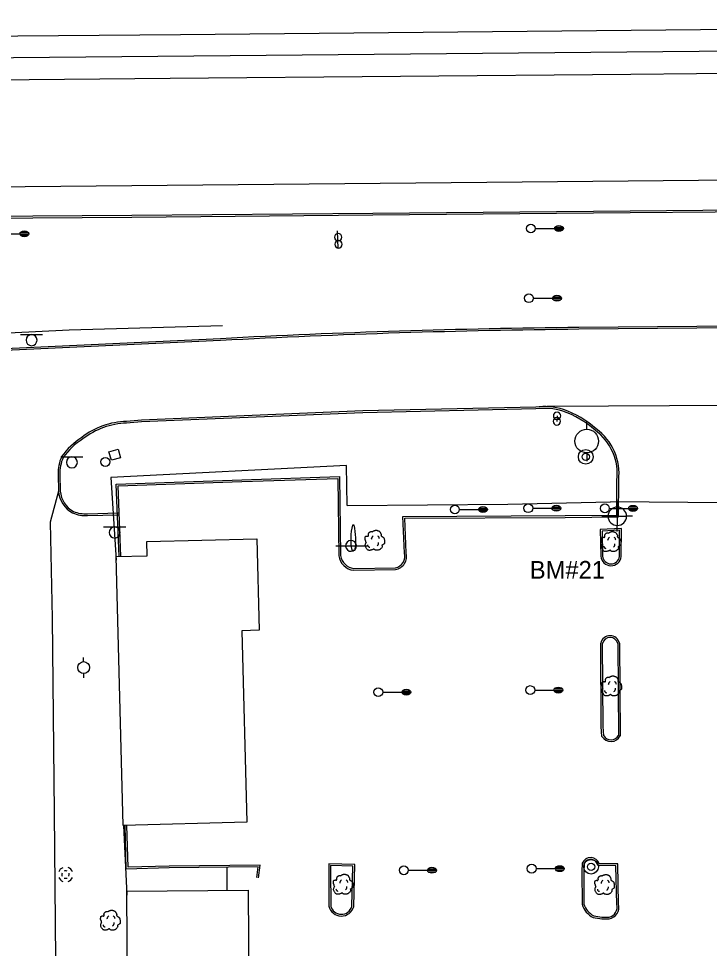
# Model space of a CAD drawing. Extents: x 2145380 to 2156929, y 139568 to 149130.
# Drawn here: x 2148024.6 to 2148258.3, y 142765.5 to 143079.9 of the extents above; entities that cross this region are included whole.
import ezdxf

# ---------------------------------------------------------------- set-up
doc = ezdxf.new("R2010")
doc.units = 0
for name, color, linetype in [('Default', 7, 'Continuous'), ('SURV_Benchmark', 7, 'Continuous'), ('SURV_Text', 7, 'Continuous'), ('TOPO_Asphalt', 7, 'Continuous'), ('TOPO_Building', 7, 'Continuous'), ('TOPO_Concrete', 7, 'Continuous'), ('TOPO_Curb Back', 7, 'Continuous'), ('TOPO_DRAIN_Manhole', 7, 'Continuous'), ('TOPO_Fence', 7, 'Continuous'), ('TOPO_Guardrail', 7, 'Continuous'), ('TOPO_Light Pole', 7, 'Continuous'), ('TOPO_Misc', 7, 'Continuous'), ('TOPO_Power Pole', 7, 'Continuous'), ('TOPO_San Manhole', 7, 'Continuous'), ('TOPO_Sign', 7, 'Continuous'), ('TOPO_Tree', 7, 'Continuous'), ('TOPO_Wall Freestanding', 7, 'Continuous'), ('TOPO_Water Meter', 7, 'Continuous')]:
    doc.layers.add(name, color=color, linetype=linetype)

# ---------------------------------------------------------------- blocks, each defined once
blk = doc.blocks.new('LP')
at = {"layer": 'TOPO_Light Pole'}
blk.add_line((3.81, 0), (20.32, 0), dxfattribs=at)
for points in [[(20.32, 0), (27.94, 0)], [(20.32, 0), (23.5, 0)], [(20.83, 1.27), (27.43, 1.27)], [(20.83, 1.27), (23.5, 1.27)], [(23.71, 1.27), (27.43, 1.27)], [(23.71, 0), (27.94, 0)], [(20.83, -1.27), (27.43, -1.27)], [(20.83, -1.27), (23.5, -1.27)], [(23.71, -1.27), (27.43, -1.27)]]:
    blk.add_lwpolyline(points, dxfattribs=at)
blk.add_circle((0, 0), 3.81, dxfattribs=at)
blk.add_ellipse((24.13, 0), major_axis=(3.81, 0), ratio=0.666667, dxfattribs=at)
blk = doc.blocks.new('POST')
at = {"layer": 'TOPO_Misc'}
for start, end in [(89.99996, 180.00004), (179.99996, 270.00004), (359.99996, 90.00004), (269.99996, 0.00004)]:
    blk.add_arc((-0.01, 0.03), 3.16, start, end, dxfattribs=at)
blk = doc.blocks.new('MHEXST')
at = {"layer": 'TOPO_DRAIN_Manhole'}
for centre, radius, start, end in [((-0.1, 0.3), 12.7, 112.9748, 158.2636), ((-0.1, 0.1), 6.35, 157.9722, 204.161), ((-0.1, 0.1), 6.35, 66.1941, 113.691), ((-0.1, 0.3), 12.7, 22.0744, 68.6991), ((-0.1, 0.1), 6.35, 336.8023, 21.4046), ((-0.1, 0.3), 12.7, 202.6921, 248.1938), ((-0.1, 0.1), 6.35, 248.5791, 293.1995), ((-0.1, 0.3), 12.7, 291.7963, 337.3032)]:
    blk.add_arc(centre, radius, start, end, dxfattribs=at)
blk = doc.blocks.new('POWPOL')
at = {"layer": 'TOPO_Power Pole'}
for p, q in [((0, 10.16), (0, 17.34)), ((0, -10.16), (0, -17.34))]:
    blk.add_line(p, q, dxfattribs=at)
blk.add_circle((0, 0), 10.16, dxfattribs=at)
blk = doc.blocks.new('TREE')
at = {"layer": 'TOPO_Tree'}
for points in [[(-14.1, -0.4), (-14.2, 0.5), (-14.4, 1.4), (-14.6, 2.3), (-14.8, 3.2), (-15.5, 4), (-15.7, 4.9), (-15.8, 5.6), (-15.7, 6.3), (-15.7, 7), (-15.6, 7.9), (-15.7, 8.8), (-15.1, 9.7), (-14.6, 10.4), (-13.8, 10.5), (-13, 10.7), (-12.2, 11), (-11.1, 10), (-10.4, 10.7), (-9.4, 11.7), (-10.3, 13.3), (-9.8, 14.4), (-9.6, 15.1), (-9.3, 15.9), (-8.8, 16.5), (-8.2, 17.3), (-7.5, 17.7), (-6.7, 18.1), (-6.1, 18.4), (-5.6, 18.6), (-5.1, 18.7), (-4.5, 18.7), (-4, 18.5), (-3.5, 18.1)], [(-3.5, 17.6), (-3.1, 18.3), (-2.6, 18.8), (-1.9, 19.2), (-1, 19.7), (-0.2, 20), (0.7, 20.2), (1.6, 20.5), (2.5, 20.8), (3.4, 20.8), (4.1, 20.7), (4.8, 20.5), (5.5, 20.2), (6.4, 19.9), (7.3, 19.7), (8.2, 19.2), (9.4, 18.4), (10, 17.2), (10.8, 16), (11.2, 15.3), (11.6, 14.6), (11.9, 13.9), (12.2, 13.1), (11.4, 12), (11.9, 11.2), (12, 11), (12.2, 10.9), (12.4, 10.7), (12.9, 10.4), (13.5, 10), (14, 9.7), (14.7, 9.2), (15.4, 8.7), (16.1, 8.1), (16.7, 7.5), (16.9, 6.7), (17.1, 6), (17.6, 4.4), (17.7, 2.8), (17.7, 1.2), (17.7, -0.2), (17.8, -2.2), (16.6, -3), (15.5, -3.8), (14.3, -4.6), (13.2, -5.3)], [(13.2, -5.3), (13.3, -5.8), (13.4, -6.3), (13.4, -6.7), (13.8, -8.5), (12.2, -10), (10.8, -11.5), (10, -12.3), (9.1, -12.8), (8.2, -13.1), (6, -13.8), (3.3, -13.6), (1.3, -13.1), (0.5, -12.9), (-0.1, -11.4), (-0.8, -11.5), (-2, -11.6), (-3.3, -12.8), (-4.5, -13.1), (-6.1, -13.5), (-7.8, -14), (-9.3, -13.6), (-11.4, -13.1), (-12.8, -11.4), (-14.1, -9.4), (-15.3, -7.3), (-15.6, -5.1), (-15.1, -3), (-14.9, -1.9), (-13.9, -0.8), (-13.5, 0.1)], [(-4.2, 5.1), (-4.5, 6.1), (-4.3, 7.2), (-3.8, 8.2), (-3.3, 9.3), (-2.7, 10.3), (-1.6, 11)], [(5.9, 11.2), (6.5, 10.7), (7, 10.2), (7.4, 9.5), (7.9, 8.6), (8.3, 7.6), (8.5, 6.6)], [(-11.4, -4.5), (-11.5, -5.4), (-11, -6.3), (-10.1, -7.2), (-9.3, -8), (-8.5, -8.3), (-7.7, -8.1)], [(4.8, -6.3), (5.7, -5.7), (6.3, -4.9), (6.8, -3.9), (7.4, -2.8), (7.6, -1.7), (7.5, -0.6)]]:
    blk.add_open_spline(points, degree=3, dxfattribs=at)
blk = doc.blocks.new('WTRMTR')
at = {"layer": 'Default'}
blk.add_circle((0, 0), 3.89, dxfattribs=at)
blk = doc.blocks.new('EXMHSS')
at = {"layer": 'Default'}
for radius in [6.3, 3.13]:
    blk.add_circle((0, 0), radius, dxfattribs=at)
blk = doc.blocks.new('BM')
at = {"layer": 'SURV_Benchmark'}
for p, q in [((0, 2.49), (0, 4.15)), ((-2.49, 0), (-4.16, 0)), ((4.16, 0), (2.49, 0)), ((0, -4.16), (0, -2.49))]:
    blk.add_line(p, q, dxfattribs=at)
for points in [[(-2.5, 0), (-2.49, 0), (0, 0), (0, -2.49), (0, -2.49)], [(-2.5, 0), (-2.49, 0), (0, 0), (0, -2.49), (0, -2.49)], [(0, 2.49), (0, 2.49), (0, 0), (2.49, 0), (2.49, 0), (2.49, 0)], [(0, 2.49), (0, 2.49), (0, 0), (2.49, 0), (2.49, 0), (2.49, 0), (2.49, 0)]]:
    blk.add_lwpolyline(points, dxfattribs=at)
for start, end in [(90.0638, 180.0068), (0.0638, 90.0068), (0.0638, 90.0068), (180.0638, 270.0068), (180.0638, 270.0068), (269.9472, 359.9927)]:
    blk.add_arc((0, 0), 2.5, start, end, dxfattribs=at)

msp = doc.modelspace()

# ---------------------------------------------------------------- linework, layer by layer
at = {"layer": 'TOPO_Asphalt'}
for p, q in [((2148286.72, 142949.26), (2148203.43, 142948.67)), ((2148095.16, 142785.11), (2148095.15, 142792.95))]:
    msp.add_line(p, q, dxfattribs=at)
for points in [[(2147470.58, 143069.33), (2147522.83, 143069.63), (2147583.04, 143070.11), (2147738.8, 143071.51), (2147927.95, 143073.19), (2148079.29, 143074.53), (2148267.02, 143076.34), (2148475.01, 143078.41), (2148538.91, 143078.92), (2148589.31, 143079.37), (2148643.94, 143079.86)], [(2148645.25, 143065.02), (2148587.42, 143064.51), (2148537.54, 143063.98), (2148499.94, 143063.7), (2148475.32, 143063.38), (2148365.01, 143062.26), (2148231.65, 143061), (2148075.9, 143059.61), (2147932.72, 143058.25), (2147796.35, 143057.04), (2147634.21, 143055.45), (2147582.22, 143054.84), (2147523.45, 143054.49), (2147473.54, 143053.84), (2147431.18, 143053.29), (2147414.12, 143053.17)], [(2147589.87, 143018.81), (2147717.93, 143020.11), (2147869.31, 143021.64), (2148038.91, 143023.21), (2148194.98, 143024.71), (2148374.01, 143026.39), (2148492.71, 143027.39), (2148574.25, 143028.13), (2148490.61, 143015.81), (2148430.33, 143006.91), (2148411.96, 143003.93)], [(2148038.06, 142920.06), (2148035.23, 142909.56), (2148035.92, 142877.2), (2148036.59, 142811.48), (2148037.06, 142761.73), (2148035.76, 142724.53), (2148048.83, 142712.9)]]:
    msp.add_lwpolyline(points, dxfattribs=at)
at = {"layer": 'TOPO_Building'}
for points in [[(2148060, 142807.05), (2148057.58, 142897.95), (2148068.06, 142898.23), (2148067.93, 142903.04), (2148105.16, 142904.03), (2148105.98, 142873.09), (2148100.05, 142872.93), (2148101.78, 142808.16)], [(2148102.22, 142785.16), (2148102.61, 142734.02), (2148061.58, 142733.7), (2148061.19, 142784.84)]]:
    msp.add_lwpolyline(points, close=True, dxfattribs=at)
at = {"layer": 'TOPO_Concrete'}
msp.add_lwpolyline([(2148058.25, 142934.32), (2148059.01, 142931.38), (2148055.95, 142930.55), (2148055.09, 142933.36), (2148058.25, 142934.32)], dxfattribs=at)
at = {"layer": 'TOPO_Curb Back'}
for p, q in [((2148228.5, 142907.48), (2148221.33, 142907.18)), ((2148221.33, 142907.18), (2148221.52, 142898.08)), ((2148227.9, 142906.86), (2148221.94, 142906.61)), ((2148221.94, 142906.61), (2148222.12, 142898.11)), ((2148227.82, 142898), (2148227.9, 142906.86)), ((2148228.42, 142897.96), (2148228.5, 142907.48)), ((2148221.7, 142840.5), (2148221.51, 142868.68)), ((2148222.3, 142840.52), (2148222.11, 142868.62)), ((2148227.26, 142868.62), (2148227.49, 142837.52)), ((2148227.86, 142868.69), (2148228.09, 142837.37)), ((2148221.93, 142837.18), (2148221.7, 142840.5)), ((2148222.52, 142837.37), (2148222.3, 142840.52)), ((2148138.29, 142793.84), (2148129.51, 142794.13)), ((2148129.51, 142794.13), (2148129.52, 142792.06)), ((2148137.68, 142793.26), (2148130.11, 142793.51)), ((2148130.11, 142793.51), (2148130.12, 142792.07)), ((2148137.34, 142779.71), (2148137.68, 142793.26)), ((2148137.93, 142779.62), (2148138.29, 142793.84)), ((2148215.28, 142794.34), (2148215.15, 142791.46)), ((2148215.88, 142794.2), (2148215.75, 142791.45)), ((2148226.66, 142793.46), (2148220.53, 142793.49)), ((2148227.25, 142794.06), (2148221.01, 142794.09)), ((2148226.96, 142780.37), (2148226.66, 142793.46)), ((2148227.56, 142780.45), (2148227.25, 142794.06)), ((2148129.52, 142792.06), (2148129.55, 142779.77)), ((2148130.12, 142792.07), (2148130.15, 142779.84)), ((2148215.15, 142791.46), (2148215.19, 142780.42)), ((2148215.75, 142791.45), (2148215.79, 142780.51)), ((2148221.89, 142775.51), (2148224.41, 142775.5)), ((2148221.94, 142776.11), (2148224.35, 142776.1))]:
    msp.add_line(p, q, dxfattribs=at)
for points in [[(2147481.17, 143008.11), (2147525.22, 143008.77), (2147576.01, 143008.92), (2147591.08, 143009.11), (2147697.75, 143010.22), (2147838.49, 143011.59), (2147962.13, 143012.69), (2148062.91, 143013.36), (2148144.44, 143014.07), (2148231.43, 143014.88), (2148317.67, 143015.61), (2148394.72, 143016.3), (2148452.05, 143016.97)], [(2147481.18, 143007.51), (2147525.22, 143008.17), (2147576.02, 143008.32), (2147591.09, 143008.51), (2147697.75, 143009.62), (2147838.5, 143010.99), (2147962.13, 143012.09), (2148062.91, 143012.76), (2148144.45, 143013.47), (2148231.43, 143014.28), (2148317.68, 143015.01), (2148394.72, 143015.7), (2148452.1, 143016.37)], [(2148286.43, 142976.24), (2148254.06, 142975.75), (2148214.13, 142975.42)], [(2148286.43, 142975.64), (2148254.06, 142975.15), (2148214.13, 142974.82)], [(2148092.84, 142971.64), (2148022.41, 142968.38), (2147893.34, 142962.43), (2147794.24, 142957.82), (2147684.33, 142952.92), (2147578.17, 142948.11)], [(2148092.87, 142971.04), (2148022.44, 142967.78), (2147893.36, 142961.84), (2147794.27, 142957.22), (2147684.36, 142952.32), (2147578.2, 142947.51)], [(2148199.53, 142948.51), (2148140.98, 142947.2), (2148066.1, 142944.1), (2148061.08, 142943.67)], [(2148199.58, 142947.91), (2148141, 142946.6), (2148066.13, 142943.5), (2148061.11, 142943.07)], [(2148037.95, 142925.7), (2148038.06, 142920.06)], [(2148038.55, 142925.72), (2148038.66, 142920.09)], [(2148058.56, 142897.97), (2148057.62, 142922.43), (2148100.06, 142923.97), (2148133.15, 142925.02), (2148133.45, 142898.29)], [(2148059.16, 142897.99), (2148058.24, 142921.86), (2148100.08, 142923.37), (2148132.56, 142924.4), (2148132.86, 142898.23)], [(2148155.08, 142899.11), (2148154.59, 142911.52), (2148209.52, 142911.84), (2148226.96, 142911.97), (2148226.98, 142923.81)], [(2148155.67, 142899.2), (2148155.22, 142910.92), (2148209.53, 142911.24), (2148227.56, 142911.37), (2148227.58, 142923.77)], [(2148047.86, 142912.43), (2148058.29, 142912.74)], [(2148047.89, 142911.83), (2148058.31, 142912.14)], [(2148137.94, 142893.35), (2148152.13, 142893.59)], [(2148137.97, 142893.95), (2148152.07, 142894.19)], [(2148105.12, 142789.44), (2148105.65, 142793.06), (2148075.52, 142792.75), (2148061.01, 142792.35), (2148060.61, 142807.06)], [(2148105.71, 142789.35), (2148106.35, 142793.67), (2148075.51, 142793.35), (2148061.59, 142792.96), (2148061.21, 142807.08)]]:
    msp.add_lwpolyline(points, dxfattribs=at)
for centre, radius, start, end in [((2148241.21, 140159.13), 2816.42, 90.55096, 93.01974), ((2148241.21, 140159.12), 2815.82, 90.55098, 93.01977), ((2148202.41, 142926.7), 21.99, 72.9151, 97.5159), ((2148202.41, 142926.7), 21.39, 72.9424, 97.6028), ((2148198.28, 142917.01), 31.89, 48.0047, 70.9491), ((2148198.28, 142917.01), 32.49, 48.0596, 70.9675), ((2148061.75, 142918.07), 25.62, 91.5079, 128.0168), ((2148061.75, 142918.07), 25.02, 91.4675, 128.0882), ((2148208.89, 142925.97), 18.22, 353.1745, 53.9631), ((2148208.89, 142925.97), 18.82, 353.2823, 53.8678), ((2148058.66, 142918), 23.9, 122.0707, 144.7843), ((2148058.66, 142918), 23.3, 121.9941, 144.639), ((2148051.79, 142926.14), 13.86, 155.9794, 181.8065), ((2148051.79, 142926.14), 13.26, 156.2324, 181.822), ((2148047.29, 142920.85), 9.27, 184.8896, 241.3022), ((2148047.29, 142920.85), 8.67, 185.0183, 241.1062), ((2148047.27, 142923.15), 11.33, 246.9741, 273.121), ((2148047.27, 142923.15), 10.73, 247.1333, 273.1607), ((2148151.29, 142898.04), 4.53, 280.6121, 14.817), ((2148138.64, 142899.17), 5.86, 189.1581, 263.1315), ((2148138.64, 142899.17), 5.26, 189.6319, 262.6955), ((2148151.29, 142898.04), 3.93, 281.3243, 15.7487), ((2148224.98, 142898.37), 3.47, 184.8868, 353.1655), ((2148224.98, 142898.37), 2.87, 185.2526, 352.5331), ((2148224.68, 142867.96), 3.26, 12.9205, 167.1848), ((2148224.68, 142867.96), 2.66, 14.2658, 165.7612), ((2148224.96, 142838.94), 3.5, 210.027, 333.4485), ((2148224.96, 142838.94), 2.9, 212.6577, 330.7328), ((2148218.1, 142793.15), 3.06, 17.7919, 157.1707), ((2148218.1, 142793.15), 2.46, 7.8675, 154.8093), ((2148133.76, 142780.76), 4.32, 193.3034, 344.7044), ((2148133.76, 142780.76), 3.72, 194.3282, 343.6238), ((2148222.02, 142782.39), 7.11, 196.1319, 244.2633), ((2148222.02, 142782.39), 6.51, 196.854, 243.5476), ((2148223.59, 142779.49), 3.48, 282.5217, 14.6162), ((2148223.59, 142779.49), 4.08, 281.5424, 13.5913), ((2148236.51, 142875.86), 100.81, 260.0686, 261.6878), ((2148236.51, 142875.86), 101.41, 260.0204, 261.7118)]:
    msp.add_arc(centre, radius, start, end, dxfattribs=at)
at = {"layer": 'TOPO_Fence'}
msp.add_line((2148264.08, 142916.15), (2148224.81, 142916.53), dxfattribs=at)
at = {"layer": 'TOPO_Guardrail'}
msp.add_line((2148060.02, 142807.05), (2148061.2, 142783.47), dxfattribs=at)
for points in [[(2147556.66, 142952.03), (2147579.97, 142952.4), (2147659.95, 142956.51), (2147754.19, 142960.96), (2147837.91, 142964.2), (2147945.71, 142969.89), (2148041.69, 142974.62), (2148093.56, 142976.12)], [(2148135.71, 142915.24), (2148135.52, 142928.73), (2148055.75, 142924.73), (2148057.61, 142896.71)], [(2148135.71, 142915.24), (2148190.04, 142915.69), (2148224.81, 142916.53)]]:
    msp.add_lwpolyline(points, dxfattribs=at)
at = {"layer": 'TOPO_Sign'}
for points in [[(2148132.72, 143002.13), (2148132.45, 143008.14)], [(2148025.2, 142973.02), (2148032.69, 142973.02)], [(2148028.95, 142973.02), (2148028.95, 142973.02)], [(2148027.08, 142971.15), (2148027.08, 142971.15)], [(2148028.95, 142969.28), (2148028.95, 142969.28)], [(2148030.82, 142971.15), (2148030.82, 142971.15)], [(2148206.73, 142945.54), (2148206.63, 142943.69)], [(2148038.84, 142931.69), (2148046.33, 142931.7)], [(2148042.59, 142931.69), (2148042.59, 142931.69)], [(2148040.72, 142929.82), (2148040.72, 142929.82)], [(2148042.59, 142927.95), (2148042.59, 142927.95)], [(2148044.46, 142929.82), (2148044.46, 142929.82)], [(2148138.05, 142908.58), (2148138.05, 142908.58), (2148137.52, 142908.63)], [(2148053.34, 142907.99), (2148060.83, 142907.99)], [(2148055.22, 142906.12), (2148055.22, 142906.12)], [(2148057.09, 142907.98), (2148057.09, 142907.98)], [(2148058.95, 142906.12), (2148058.95, 142906.12)], [(2148057.09, 142904.25), (2148057.09, 142904.25)], [(2148131.9, 142901.57), (2148142.78, 142901.63)], [(2148137.27, 142900.19), (2148138.32, 142900.09), (2148138.32, 142900.09)]]:
    msp.add_lwpolyline(points, dxfattribs=at)
for centre, radius, start, end in [((2148028.95, 142971.15), 1.87, 90, 180), ((2148028.95, 142971.15), 1.87, 360, 90), ((2148028.95, 142971.15), 1.87, 180, 270), ((2148028.95, 142971.15), 1.87, 270, 0), ((2148042.59, 142929.82), 1.87, 90, 180), ((2148042.59, 142929.82), 1.87, 360, 90), ((2148042.59, 142929.82), 1.87, 180, 270), ((2148042.59, 142929.82), 1.87, 270, 0), ((2148157.04, 142903.82), 20.1, 166.1576, 190.4271), ((2148057.09, 142906.12), 1.87, 90, 180), ((2148057.09, 142906.12), 1.87, 180, 270), ((2148057.09, 142906.12), 1.87, 360, 90), ((2148057.09, 142906.12), 1.87, 270, 0), ((2148118.65, 142903.71), 20.01, 349.5558, 14.0793), ((2148137.04, 142901.59), 1.84, 47.4196, 227.4196), ((2148137.04, 142901.59), 1.84, 227.4196, 47.4196)]:
    msp.add_arc(centre, radius, start, end, dxfattribs=at)
at = {"layer": 'TOPO_Wall Freestanding'}
msp.add_lwpolyline([(2147479.18, 143063.5), (2147502.44, 143062.76), (2147568.05, 143062.22), (2147732.59, 143064.04), (2147961.74, 143066.11), (2148279.21, 143069.09), (2148468.28, 143071.01), (2148647.08, 143072.36)], dxfattribs=at)

# ---------------------------------------------------------------- block references
at = {"layer": 'SURV_Benchmark', "xscale": 1.25, "yscale": 1.25}
msp.add_blockref('BM', (2148227.11, 142911.61), dxfattribs=at)
at = {"layer": 'TOPO_DRAIN_Manhole', "xscale": 0.19685000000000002, "yscale": 0.19685000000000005}
msp.add_blockref('MHEXST', (2148040.48, 142790.44), dxfattribs=at)
at = {"layer": 'TOPO_Light Pole', "xscale": 0.39370000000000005, "yscale": 0.3937000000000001}
for p in [(2148197.87, 143008.9), (2148017.03, 143007.11), (2148197.21, 142985.33), (2148172.17, 142913.89), (2148196.99, 142914.33), (2148222.91, 142914.27), (2148146.25, 142852.14), (2148197.67, 142852.84), (2148154.9, 142791.93), (2148198.15, 142792.47)]:
    msp.add_blockref('LP', p, dxfattribs=at)
at = {"layer": 'TOPO_Misc', "xscale": 0.39370000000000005, "yscale": 0.3937000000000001}
for p in [(2148132.66, 143005.92), (2148132.79, 143003.53), (2148206.73, 142945.54), (2148206.63, 142943.69)]:
    msp.add_blockref('POST', p, dxfattribs=at)
at = {"layer": 'TOPO_Power Pole'}
for p, xscale, yscale in [((2148216.77, 142937.03), 0.39370000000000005, 0.3937000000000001), ((2148046.58, 142860.45), 0.19685000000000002, 0.19685000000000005)]:
    msp.add_blockref('POWPOL', p, dxfattribs=dict(at, xscale=xscale, yscale=yscale))
at = {"layer": 'TOPO_San Manhole', "xscale": 0.39370000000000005, "yscale": 0.3937000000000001}
for p in [(2148216.44, 142931.7), (2148218.24, 142793.1)]:
    msp.add_blockref('EXMHSS', p, dxfattribs=at)
at = {"layer": 'TOPO_Tree', "xscale": 0.19685000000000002, "yscale": 0.19685000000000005}
for p in [(2148144.88, 142902.8), (2148224.83, 142902.37), (2148225.04, 142853.57), (2148134.18, 142786.52), (2148222.62, 142786.43), (2148055.42, 142774.36)]:
    msp.add_blockref('TREE', p, dxfattribs=at)
at = {"layer": 'TOPO_Water Meter', "xscale": 0.39370000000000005, "yscale": 0.3937000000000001}
msp.add_blockref('WTRMTR', (2148053.92, 142929.99), dxfattribs=at)

# ---------------------------------------------------------------- texts
at = {"layer": 'SURV_Text'}
msp.add_text('BM#21', height=6, dxfattribs=at).set_placement((2148197.52, 142890.49))

doc.saveas('drawing.dxf')
